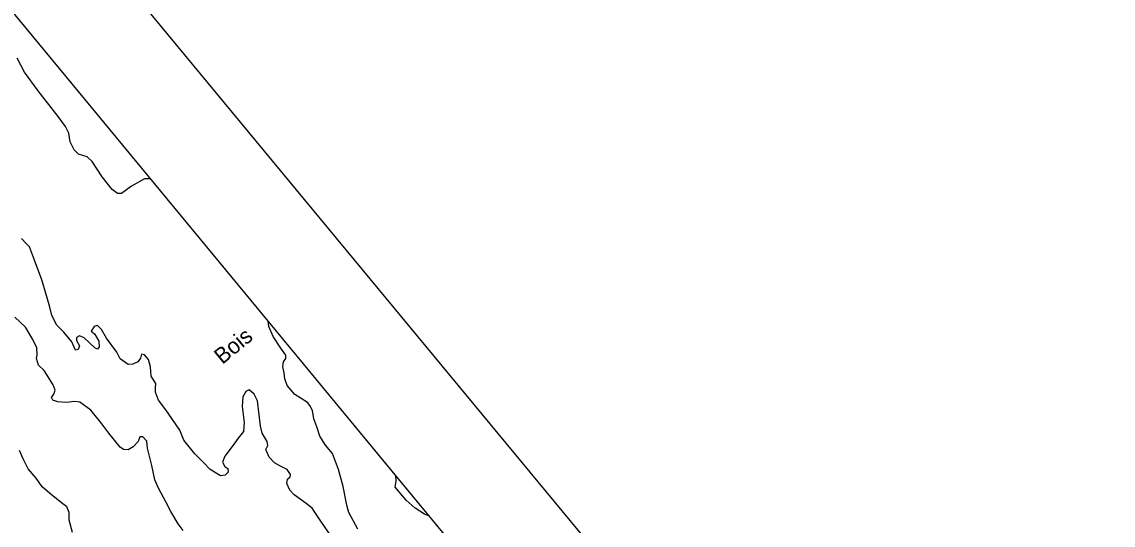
# Model space of a CAD drawing. Extents: x 347059 to 352153, y 6073752 to 6078601.
# Drawn here: x 351068.9 to 351378.9, y 6076283.3 to 6076426.2 of the extents above; entities that cross this region are included whole.
import ezdxf

# ---------------------------------------------------------------- set-up
doc = ezdxf.new("R2010")
doc.units = 0
for name, color, linetype in [('Level 1', 7, 'Continuous'), ('Level 2', 7, 'Continuous'), ('Level 44', 7, 'Continuous'), ('Level 60', 7, 'Continuous')]:
    doc.layers.add(name, color=color, linetype=linetype)

msp = doc.modelspace()

# ---------------------------------------------------------------- linework, layer by layer
at = {"layer": 'Level 1'}
msp.add_lwpolyline([(351083.34, 6076281.13), (351082.31, 6076284.68), (351082.33, 6076286.85), (351081.65, 6076288.42), (351080.22, 6076289.62), (351076.8, 6076292.35), (351074.69, 6076294.17), (351072.99, 6076296.62), (351070.73, 6076299.26), (351069.27, 6076302.05), (351068.29, 6076304.44)], dxfattribs=at)
at = {"layer": 'Level 2'}
for points in [[(351100.1, 6076379.55), (351097.2, 6076377.47), (351096.05, 6076377.42), (351094.54, 6076378.54), (351091.72, 6076382.15), (351088.88, 6076386.55), (351087.46, 6076387.88), (351084.99, 6076388.58), (351083.79, 6076389.83), (351082.6, 6076392.15), (351082.27, 6076394.56), (351081.33, 6076396.43), (351079.25, 6076399.33), (351073.52, 6076406.62), (351069.67, 6076411.89), (351067.59, 6076415.87)], [(351105.66, 6076381.47), (351105.3, 6076381.59), (351103.79, 6076381.64), (351100.1, 6076379.55)], [(351091.52, 6076338.87), (351090.45, 6076339.96), (351089.49, 6076339.67), (351088.59, 6076338.37), (351089.55, 6076337.58), (351090.76, 6076335.54), (351090.85, 6076333.87), (351090.45, 6076333.25), (351089.61, 6076333.61), (351086.64, 6076336.43), (351085.32, 6076337.04), (351084.41, 6076336.54), (351084.42, 6076335.74), (351085.32, 6076334.23), (351084.94, 6076333.1), (351084.14, 6076332.95), (351083.16, 6076335.33), (351080.84, 6076338.04), (351078.83, 6076340.07), (351077.44, 6076342.78), (351076.9, 6076345.13), (351076.09, 6076347.79), (351074.6, 6076352.96), (351072.5, 6076358.53), (351071.12, 6076362.32), (351070.18, 6076363.26), (351068.84, 6076364.66)], [(351101.96, 6076306.97), (351100.55, 6076305.49), (351099.11, 6076304.66), (351097.82, 6076304.76), (351096.85, 6076305.41), (351093.61, 6076309.35), (351091.38, 6076312.41), (351088.47, 6076315.96), (351085.38, 6076318.16), (351083.95, 6076318.41), (351081.54, 6076318.09), (351079.09, 6076318.28), (351077.75, 6076318.75), (351077.37, 6076319.5), (351078.03, 6076320.46), (351078.4, 6076321.59), (351077.79, 6076323.08), (351075.21, 6076327.18), (351073.66, 6076328.68), (351073.08, 6076330.6), (351073.3, 6076331.6), (351073.16, 6076333.63), (351072.04, 6076336.03), (351069.91, 6076339.45), (351066.88, 6076342.36)], [(351164.35, 6076282.1), (351161.83, 6076286.9), (351161.27, 6076288.96), (351160.23, 6076294.23), (351158.86, 6076299.08), (351157.12, 6076303.61), (351155.13, 6076305.93), (351153.6, 6076308.49), (351152.72, 6076311.22), (351151.88, 6076313.45), (351151.48, 6076315.78), (351150.73, 6076317.28), (351150.07, 6076318.05), (351146.5, 6076320.35), (351144.31, 6076322.89), (351143.59, 6076324.82), (351143.44, 6076326.56), (351143.06, 6076328.25), (351143.23, 6076329.6), (351143.88, 6076330.56), (351143.88, 6076331.49), (351142.52, 6076333.54), (351140.33, 6076336.88), (351139.1, 6076339.71), (351138.9, 6076341.24)], [(351156.93, 6076279.84), (351153.81, 6076284.41), (351151.34, 6076288.06), (351149.64, 6076289.42), (351146.22, 6076291.85), (351145.03, 6076293.24), (351144.23, 6076295.1), (351144.39, 6076296.31), (351145.16, 6076296.98), (351145.22, 6076297.69), (351144.31, 6076299.06), (351142.22, 6076300.09), (351140.7, 6076300.93), (351139.16, 6076302.56), (351138.24, 6076304.72), (351138.76, 6076305.84), (351138.56, 6076307.01), (351137.16, 6076309.42), (351136.66, 6076311.41), (351136.32, 6076314.61), (351135.83, 6076318.61), (351134.89, 6076320.49), (351133.46, 6076321.68), (351132.49, 6076321.25), (351131.66, 6076319.73), (351131.52, 6076316.93), (351132.04, 6076312.42), (351131.85, 6076309.84), (351130.4, 6076307.93), (351128.64, 6076305.61), (351126.56, 6076302.89), (351125.92, 6076301.14), (351126.55, 6076299.93), (351127.45, 6076299.36), (351127.51, 6076298.34), (351126.65, 6076297.47), (351125.34, 6076297.29), (351122.37, 6076299.03), (351120.57, 6076300.97), (351118.01, 6076303.48), (351114.92, 6076307.4), (351113.83, 6076310.22), (351111.49, 6076313.58), (351109.79, 6076316.02), (351107.69, 6076318.78), (351106.85, 6076321.01), (351106.87, 6076322.24), (351106.97, 6076323.53), (351105.61, 6076325.58), (351105.45, 6076328.26), (351104.88, 6076330.32), (351103.76, 6076331.64), (351102.9, 6076331.85), (351102.6, 6076330.65), (351101.87, 6076329.62), (351100.45, 6076328.94), (351099.14, 6076328.9), (351096.81, 6076330.52), (351095.87, 6076332.4), (351092.99, 6076336.37), (351091.52, 6076338.87)], [(351114.74, 6076281.77), (351113.36, 6076283.68), (351111.23, 6076287.1), (351109.78, 6076289.89), (351107.76, 6076293.8), (351106.71, 6076296.12), (351105.79, 6076300.17), (351104.64, 6076305.1), (351104.43, 6076307.07), (351103.3, 6076308.38), (351102.43, 6076308.3), (351101.96, 6076306.97)], [(351184.68, 6076285.84), (351183.26, 6076286.34), (351180.59, 6076288.06), (351178.1, 6076290.33), (351175, 6076294.09), (351175.2, 6076295.73), (351175.13, 6076297.4)]]:
    msp.add_lwpolyline(points, dxfattribs=at)
at = {"layer": 'Level 60'}
for points in [[(349811.7, 6077991.51), (350486.88, 6078550.39), (352105.73, 6076594.68), (351430.55, 6076035.79)], [(347109.95, 6075761.81), (348728.53, 6073803.05), (351407.22, 6076016.53), (349788.63, 6077975.29)]]:
    msp.add_lwpolyline(points, close=True, dxfattribs=at)

# ---------------------------------------------------------------- texts
at = {"layer": 'Level 44'}
msp.add_text('Bois', height=4.5, rotation=39.568, dxfattribs=at).set_placement((351125.87, 6076328.75))

doc.saveas('drawing.dxf')
